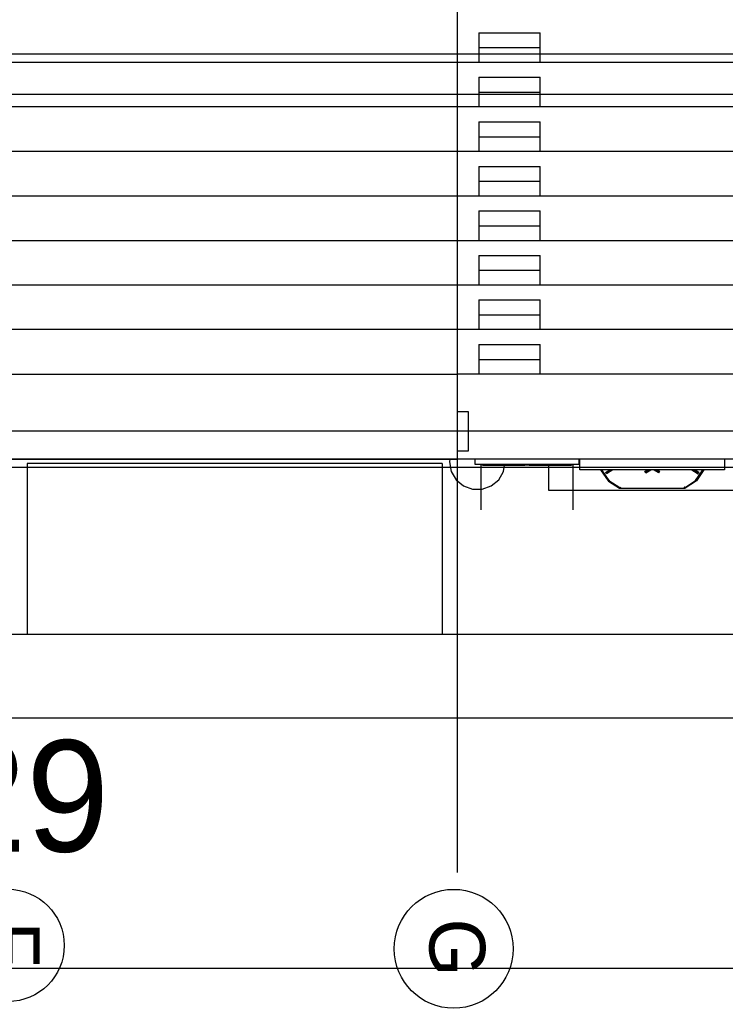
# Model space of a CAD drawing. Extents: x -264165 to -263575, y -1242333 to -1242036.
# Drawn here: x -263884.32 to -263871.66, y -1242251.17 to -1242233.41 of the extents above; entities that cross this region are included whole.
import ezdxf

# ---------------------------------------------------------------- set-up
doc = ezdxf.new("R2010")
doc.units = 0
for name, color, linetype in [('KFA_BODY_VYTYCOVAK', 7, 'Continuous'), ('KFA_HESCON_OSI_STAVBY', 7, 'Continuous'), ('KFA_SITUACIA_DRS_VYTYCOVAK_SEDA', 7, 'Continuous')]:
    doc.layers.add(name, color=color, linetype=linetype)

msp = doc.modelspace()

# ---------------------------------------------------------------- linework, layer by layer
at = {"layer": 'KFA_HESCON_OSI_STAVBY'}
for p, q in [((-263876.468, -1242080.447), (-263876.468, -1242248.737)), ((-263787.486, -1242234.032), (-263921.823, -1242234.032)), ((-263787.486, -1242240.807), (-263921.823, -1242240.807))]:
    msp.add_line(p, q, dxfattribs=at)
for centre, radius in [((-263884.533, -1242250.045), 1.008), ((-263876.533, -1242250.106), 1.068)]:
    msp.add_circle(centre, radius, dxfattribs=at)
at = {"layer": 'KFA_SITUACIA_DRS_VYTYCOVAK_SEDA'}
for p, q in [((-263876.081, -1242233.649), (-263876.081, -1242233.916)), ((-263876.081, -1242233.649), (-263876.081, -1242233.916)), ((-263876.081, -1242233.649), (-263874.981, -1242233.649)), ((-263876.081, -1242233.649), (-263874.981, -1242233.649)), ((-263874.981, -1242233.916), (-263874.981, -1242233.649)), ((-263874.981, -1242233.916), (-263874.981, -1242233.649)), ((-263876.081, -1242233.916), (-263874.981, -1242233.916)), ((-263876.081, -1242233.916), (-263874.981, -1242233.916)), ((-263876.081, -1242233.916), (-263876.081, -1242234.182)), ((-263876.081, -1242233.916), (-263876.081, -1242234.182)), ((-263874.981, -1242234.182), (-263874.981, -1242233.916)), ((-263874.981, -1242234.182), (-263874.981, -1242233.916)), ((-263876.468, -1242234.182), (-263884.468, -1242234.182)), ((-263876.468, -1242234.182), (-263884.468, -1242234.182)), ((-263869.468, -1242234.182), (-263876.468, -1242234.182)), ((-263869.468, -1242234.182), (-263876.468, -1242234.182)), ((-263876.081, -1242234.449), (-263876.081, -1242234.716)), ((-263876.081, -1242234.449), (-263876.081, -1242234.716)), ((-263876.081, -1242234.449), (-263874.981, -1242234.449)), ((-263876.081, -1242234.449), (-263874.981, -1242234.449)), ((-263874.981, -1242234.716), (-263874.981, -1242234.449)), ((-263874.981, -1242234.716), (-263874.981, -1242234.449)), ((-263876.081, -1242234.716), (-263874.981, -1242234.716)), ((-263876.081, -1242234.716), (-263874.981, -1242234.716)), ((-263876.081, -1242234.716), (-263876.081, -1242234.982)), ((-263876.081, -1242234.716), (-263876.081, -1242234.982)), ((-263874.981, -1242234.982), (-263874.981, -1242234.716)), ((-263874.981, -1242234.982), (-263874.981, -1242234.716)), ((-263812.068, -1242234.757), (-263891.868, -1242234.757)), ((-263876.468, -1242234.982), (-263884.468, -1242234.982)), ((-263876.468, -1242234.982), (-263884.468, -1242234.982)), ((-263869.468, -1242234.982), (-263876.468, -1242234.982)), ((-263869.468, -1242234.982), (-263876.468, -1242234.982)), ((-263876.081, -1242235.249), (-263876.081, -1242235.516)), ((-263876.081, -1242235.249), (-263876.081, -1242235.516)), ((-263876.081, -1242235.249), (-263874.981, -1242235.249)), ((-263876.081, -1242235.249), (-263874.981, -1242235.249)), ((-263874.981, -1242235.516), (-263874.981, -1242235.249)), ((-263874.981, -1242235.516), (-263874.981, -1242235.249)), ((-263876.081, -1242235.516), (-263874.981, -1242235.516)), ((-263876.081, -1242235.516), (-263874.981, -1242235.516)), ((-263876.081, -1242235.516), (-263876.081, -1242235.782)), ((-263876.081, -1242235.516), (-263876.081, -1242235.782)), ((-263874.981, -1242235.782), (-263874.981, -1242235.516)), ((-263874.981, -1242235.782), (-263874.981, -1242235.516)), ((-263876.468, -1242235.782), (-263884.468, -1242235.782)), ((-263876.468, -1242235.782), (-263884.468, -1242235.782)), ((-263869.468, -1242235.782), (-263876.468, -1242235.782)), ((-263869.468, -1242235.782), (-263876.468, -1242235.782)), ((-263876.081, -1242236.049), (-263876.081, -1242236.316)), ((-263876.081, -1242236.049), (-263876.081, -1242236.316)), ((-263876.081, -1242236.049), (-263874.981, -1242236.049)), ((-263876.081, -1242236.049), (-263874.981, -1242236.049)), ((-263874.981, -1242236.316), (-263874.981, -1242236.049)), ((-263874.981, -1242236.316), (-263874.981, -1242236.049)), ((-263876.081, -1242236.316), (-263874.981, -1242236.316)), ((-263876.081, -1242236.316), (-263874.981, -1242236.316)), ((-263876.081, -1242236.316), (-263876.081, -1242236.582)), ((-263876.081, -1242236.316), (-263876.081, -1242236.582)), ((-263874.981, -1242236.582), (-263874.981, -1242236.316)), ((-263874.981, -1242236.582), (-263874.981, -1242236.316)), ((-263876.468, -1242236.582), (-263884.468, -1242236.582)), ((-263876.468, -1242236.582), (-263884.468, -1242236.582)), ((-263869.468, -1242236.582), (-263876.468, -1242236.582)), ((-263869.468, -1242236.582), (-263876.468, -1242236.582)), ((-263876.081, -1242236.849), (-263876.081, -1242237.116)), ((-263876.081, -1242236.849), (-263876.081, -1242237.116)), ((-263876.081, -1242236.849), (-263874.981, -1242236.849)), ((-263876.081, -1242236.849), (-263874.981, -1242236.849)), ((-263874.981, -1242237.116), (-263874.981, -1242236.849)), ((-263874.981, -1242237.116), (-263874.981, -1242236.849)), ((-263876.081, -1242237.116), (-263874.981, -1242237.116)), ((-263876.081, -1242237.116), (-263874.981, -1242237.116)), ((-263876.081, -1242237.116), (-263876.081, -1242237.382)), ((-263876.081, -1242237.116), (-263876.081, -1242237.382)), ((-263874.981, -1242237.382), (-263874.981, -1242237.116)), ((-263874.981, -1242237.382), (-263874.981, -1242237.116)), ((-263884.468, -1242237.382), (-263876.468, -1242237.382)), ((-263884.468, -1242237.382), (-263876.468, -1242237.382)), ((-263876.468, -1242237.382), (-263869.468, -1242237.382)), ((-263876.468, -1242237.382), (-263869.468, -1242237.382)), ((-263876.081, -1242237.649), (-263876.081, -1242237.916)), ((-263876.081, -1242237.649), (-263876.081, -1242237.916)), ((-263876.081, -1242237.649), (-263874.981, -1242237.649)), ((-263876.081, -1242237.649), (-263874.981, -1242237.649)), ((-263874.981, -1242237.916), (-263874.981, -1242237.649)), ((-263874.981, -1242237.916), (-263874.981, -1242237.649)), ((-263876.081, -1242237.916), (-263874.981, -1242237.916)), ((-263876.081, -1242237.916), (-263874.981, -1242237.916)), ((-263876.081, -1242237.916), (-263876.081, -1242238.182)), ((-263876.081, -1242237.916), (-263876.081, -1242238.182)), ((-263874.981, -1242238.182), (-263874.981, -1242237.916)), ((-263874.981, -1242238.182), (-263874.981, -1242237.916)), ((-263876.468, -1242238.182), (-263884.468, -1242238.182)), ((-263876.468, -1242238.182), (-263884.468, -1242238.182)), ((-263869.468, -1242238.182), (-263876.468, -1242238.182)), ((-263869.468, -1242238.182), (-263876.468, -1242238.182)), ((-263876.081, -1242238.449), (-263876.081, -1242238.716)), ((-263876.081, -1242238.449), (-263876.081, -1242238.716)), ((-263876.081, -1242238.449), (-263874.981, -1242238.449)), ((-263876.081, -1242238.449), (-263874.981, -1242238.449)), ((-263874.981, -1242238.716), (-263874.981, -1242238.449)), ((-263874.981, -1242238.716), (-263874.981, -1242238.449)), ((-263876.081, -1242238.716), (-263874.981, -1242238.716)), ((-263876.081, -1242238.716), (-263874.981, -1242238.716)), ((-263876.081, -1242238.716), (-263876.081, -1242238.982)), ((-263876.081, -1242238.716), (-263876.081, -1242238.982)), ((-263874.981, -1242238.982), (-263874.981, -1242238.716)), ((-263874.981, -1242238.982), (-263874.981, -1242238.716)), ((-263876.468, -1242238.982), (-263884.468, -1242238.982)), ((-263876.468, -1242238.982), (-263884.468, -1242238.982)), ((-263869.468, -1242238.982), (-263876.468, -1242238.982)), ((-263869.468, -1242238.982), (-263876.468, -1242238.982)), ((-263876.081, -1242239.249), (-263876.081, -1242239.516)), ((-263876.081, -1242239.249), (-263876.081, -1242239.516)), ((-263876.081, -1242239.249), (-263874.981, -1242239.249)), ((-263876.081, -1242239.249), (-263874.981, -1242239.249)), ((-263874.981, -1242239.516), (-263874.981, -1242239.249)), ((-263874.981, -1242239.516), (-263874.981, -1242239.249)), ((-263876.081, -1242239.516), (-263874.981, -1242239.516)), ((-263876.081, -1242239.516), (-263874.981, -1242239.516)), ((-263876.081, -1242239.516), (-263876.081, -1242239.782)), ((-263876.081, -1242239.516), (-263876.081, -1242239.782)), ((-263874.981, -1242239.782), (-263874.981, -1242239.516)), ((-263874.981, -1242239.782), (-263874.981, -1242239.516)), ((-263884.468, -1242239.782), (-263876.468, -1242239.782)), ((-263884.468, -1242239.782), (-263876.468, -1242239.782)), ((-263869.468, -1242239.782), (-263876.468, -1242239.782)), ((-263869.468, -1242239.782), (-263876.468, -1242239.782)), ((-263876.268, -1242240.457), (-263876.468, -1242240.457)), ((-263876.268, -1242240.457), (-263876.468, -1242240.457)), ((-263876.468, -1242240.457), (-263876.468, -1242241.157)), ((-263876.468, -1242240.457), (-263876.468, -1242241.157)), ((-263876.268, -1242241.157), (-263876.268, -1242240.457)), ((-263876.268, -1242241.157), (-263876.268, -1242240.457)), ((-263884.468, -1242241.307), (-263876.468, -1242241.307)), ((-263884.468, -1242241.307), (-263876.468, -1242241.307)), ((-263876.478, -1242241.307), (-263884.458, -1242241.307)), ((-263876.478, -1242241.307), (-263884.458, -1242241.307)), ((-263876.599, -1242241.307), (-263876.608, -1242241.357)), ((-263876.599, -1242241.307), (-263876.608, -1242241.357)), ((-263876.458, -1242241.307), (-263876.478, -1242241.307)), ((-263876.458, -1242241.307), (-263876.478, -1242241.307)), ((-263876.468, -1242241.157), (-263876.268, -1242241.157)), ((-263876.468, -1242241.157), (-263876.268, -1242241.157)), ((-263869.468, -1242241.307), (-263876.468, -1242241.307)), ((-263869.468, -1242241.307), (-263876.468, -1242241.307)), ((-263869.478, -1242241.307), (-263876.458, -1242241.307)), ((-263869.478, -1242241.307), (-263876.458, -1242241.307)), ((-263876.148, -1242241.407), (-263876.148, -1242241.307)), ((-263876.148, -1242241.407), (-263876.148, -1242241.307)), ((-263874.288, -1242241.307), (-263874.288, -1242241.407)), ((-263874.288, -1242241.307), (-263874.288, -1242241.407)), ((-263874.268, -1242241.503), (-263874.268, -1242241.307)), ((-263874.268, -1242241.503), (-263874.268, -1242241.307)), ((-263871.668, -1242241.307), (-263871.668, -1242241.503)), ((-263871.668, -1242241.307), (-263871.668, -1242241.503)), ((-263808.968, -1242241.457), (-263894.968, -1242241.457)), ((-263884.188, -1242241.388), (-263884.188, -1242244.458)), ((-263884.188, -1242241.388), (-263884.188, -1242244.458)), ((-263876.738, -1242241.388), (-263884.188, -1242241.388)), ((-263876.738, -1242241.388), (-263884.188, -1242241.388)), ((-263876.738, -1242241.388), (-263876.738, -1242244.458)), ((-263876.738, -1242241.388), (-263876.738, -1242244.458)), ((-263876.608, -1242241.357), (-263876.578, -1242241.528)), ((-263876.608, -1242241.357), (-263876.578, -1242241.528)), ((-263874.288, -1242241.407), (-263876.148, -1242241.407)), ((-263874.288, -1242241.407), (-263876.148, -1242241.407)), ((-263876.043, -1242241.407), (-263876.043, -1242242.222)), ((-263876.043, -1242241.407), (-263876.043, -1242242.222)), ((-263876.043, -1242241.407), (-263876.017, -1242241.407)), ((-263876.043, -1242241.407), (-263876.017, -1242241.407)), ((-263876.017, -1242241.417), (-263876.017, -1242241.407)), ((-263876.017, -1242241.417), (-263876.017, -1242241.407)), ((-263876.017, -1242241.417), (-263875.258, -1242241.417)), ((-263876.017, -1242241.417), (-263875.258, -1242241.417)), ((-263875.638, -1242241.528), (-263875.618, -1242241.417)), ((-263875.638, -1242241.528), (-263875.618, -1242241.417)), ((-263875.258, -1242241.417), (-263875.258, -1242241.407)), ((-263875.258, -1242241.417), (-263875.258, -1242241.407)), ((-263875.258, -1242241.407), (-263875.228, -1242241.407)), ((-263875.258, -1242241.407), (-263875.228, -1242241.407)), ((-263875.258, -1242241.417), (-263875.258, -1242241.407)), ((-263875.258, -1242241.417), (-263875.258, -1242241.407)), ((-263875.178, -1242241.417), (-263875.258, -1242241.417)), ((-263875.178, -1242241.417), (-263875.258, -1242241.417)), ((-263875.208, -1242241.407), (-263875.177, -1242241.407)), ((-263875.208, -1242241.407), (-263875.177, -1242241.407)), ((-263875.178, -1242241.407), (-263875.178, -1242241.417)), ((-263875.178, -1242241.407), (-263875.178, -1242241.417)), ((-263875.177, -1242241.407), (-263875.177, -1242241.417)), ((-263875.177, -1242241.407), (-263875.177, -1242241.417)), ((-263875.177, -1242241.417), (-263874.418, -1242241.417)), ((-263875.177, -1242241.417), (-263874.418, -1242241.417)), ((-263874.828, -1242241.417), (-263874.828, -1242241.868)), ((-263874.828, -1242241.417), (-263874.828, -1242241.868)), ((-263874.418, -1242241.407), (-263874.393, -1242241.407)), ((-263874.418, -1242241.407), (-263874.393, -1242241.407)), ((-263874.418, -1242241.407), (-263874.418, -1242241.417)), ((-263874.418, -1242241.407), (-263874.418, -1242241.417)), ((-263874.393, -1242241.407), (-263874.393, -1242242.222)), ((-263874.393, -1242241.407), (-263874.393, -1242242.222)), ((-263876.578, -1242241.528), (-263876.491, -1242241.679)), ((-263876.578, -1242241.528), (-263876.491, -1242241.679)), ((-263875.725, -1242241.679), (-263875.638, -1242241.528)), ((-263875.725, -1242241.679), (-263875.638, -1242241.528)), ((-263871.668, -1242241.503), (-263874.268, -1242241.503)), ((-263871.668, -1242241.503), (-263874.268, -1242241.503)), ((-263873.889, -1242241.503), (-263873.754, -1242241.702)), ((-263873.889, -1242241.503), (-263873.754, -1242241.702)), ((-263873.754, -1242241.701), (-263873.889, -1242241.503)), ((-263873.754, -1242241.701), (-263873.889, -1242241.503)), ((-263873.877, -1242241.503), (-263873.746, -1242241.694)), ((-263873.877, -1242241.503), (-263873.746, -1242241.694)), ((-263873.873, -1242241.507), (-263873.874, -1242241.507)), ((-263873.873, -1242241.507), (-263873.874, -1242241.507)), ((-263873.873, -1242241.508), (-263873.874, -1242241.508)), ((-263873.873, -1242241.508), (-263873.874, -1242241.508)), ((-263873.872, -1242241.503), (-263873.873, -1242241.508)), ((-263873.872, -1242241.503), (-263873.873, -1242241.508)), ((-263873.872, -1242241.503), (-263873.873, -1242241.507)), ((-263873.872, -1242241.503), (-263873.873, -1242241.507)), ((-263873.806, -1242241.546), (-263873.732, -1242241.503)), ((-263873.806, -1242241.546), (-263873.732, -1242241.503)), ((-263873.806, -1242241.546), (-263873.797, -1242241.561)), ((-263873.806, -1242241.546), (-263873.797, -1242241.561)), ((-263873.797, -1242241.561), (-263873.698, -1242241.503)), ((-263873.797, -1242241.561), (-263873.698, -1242241.503)), ((-263873.792, -1242241.57), (-263873.797, -1242241.561)), ((-263873.792, -1242241.57), (-263873.797, -1242241.561)), ((-263873.677, -1242241.503), (-263873.792, -1242241.57)), ((-263873.677, -1242241.503), (-263873.792, -1242241.57)), ((-263873.047, -1242241.503), (-263873.099, -1242241.533)), ((-263873.047, -1242241.503), (-263873.099, -1242241.533)), ((-263873.099, -1242241.533), (-263873.047, -1242241.503)), ((-263873.099, -1242241.533), (-263873.047, -1242241.503)), ((-263873.099, -1242241.533), (-263873.093, -1242241.543)), ((-263873.099, -1242241.533), (-263873.093, -1242241.543)), ((-263873.093, -1242241.543), (-263873.099, -1242241.533)), ((-263873.093, -1242241.543), (-263873.099, -1242241.533)), ((-263873.025, -1242241.503), (-263873.093, -1242241.543)), ((-263873.025, -1242241.503), (-263873.093, -1242241.543)), ((-263873.085, -1242241.557), (-263873.093, -1242241.543)), ((-263873.085, -1242241.557), (-263873.093, -1242241.543)), ((-263873.085, -1242241.557), (-263873.093, -1242241.543)), ((-263873.085, -1242241.557), (-263873.093, -1242241.543)), ((-263873.085, -1242241.557), (-263872.991, -1242241.503)), ((-263873.085, -1242241.557), (-263872.991, -1242241.503)), ((-263872.85, -1242241.557), (-263872.943, -1242241.503)), ((-263872.85, -1242241.557), (-263872.943, -1242241.503)), ((-263872.841, -1242241.543), (-263872.909, -1242241.503)), ((-263872.841, -1242241.543), (-263872.909, -1242241.503)), ((-263872.888, -1242241.503), (-263872.836, -1242241.533)), ((-263872.888, -1242241.503), (-263872.836, -1242241.533)), ((-263872.836, -1242241.533), (-263872.888, -1242241.503)), ((-263872.836, -1242241.533), (-263872.888, -1242241.503)), ((-263872.85, -1242241.557), (-263872.841, -1242241.543)), ((-263872.85, -1242241.557), (-263872.841, -1242241.543)), ((-263872.85, -1242241.557), (-263872.841, -1242241.543)), ((-263872.85, -1242241.557), (-263872.841, -1242241.543)), ((-263872.836, -1242241.533), (-263872.841, -1242241.543)), ((-263872.836, -1242241.533), (-263872.841, -1242241.543)), ((-263872.841, -1242241.543), (-263872.836, -1242241.533)), ((-263872.841, -1242241.543), (-263872.836, -1242241.533)), ((-263872.258, -1242241.503), (-263872.143, -1242241.57)), ((-263872.258, -1242241.503), (-263872.143, -1242241.57)), ((-263872.237, -1242241.503), (-263872.137, -1242241.561)), ((-263872.237, -1242241.503), (-263872.137, -1242241.561)), ((-263872.129, -1242241.546), (-263872.203, -1242241.503)), ((-263872.129, -1242241.546), (-263872.203, -1242241.503)), ((-263872.189, -1242241.694), (-263872.058, -1242241.503)), ((-263872.189, -1242241.694), (-263872.058, -1242241.503)), ((-263872.183, -1242241.694), (-263872.052, -1242241.503)), ((-263872.183, -1242241.694), (-263872.052, -1242241.503)), ((-263872.04, -1242241.503), (-263872.175, -1242241.701)), ((-263872.04, -1242241.503), (-263872.175, -1242241.701)), ((-263872.143, -1242241.57), (-263872.137, -1242241.561)), ((-263872.143, -1242241.57), (-263872.137, -1242241.561)), ((-263872.129, -1242241.546), (-263872.137, -1242241.561)), ((-263872.129, -1242241.546), (-263872.137, -1242241.561)), ((-263872.063, -1242241.503), (-263872.061, -1242241.508)), ((-263872.063, -1242241.503), (-263872.061, -1242241.508)), ((-263872.061, -1242241.508), (-263872.061, -1242241.508)), ((-263872.061, -1242241.508), (-263872.061, -1242241.508)), ((-263876.491, -1242241.679), (-263876.358, -1242241.79)), ((-263876.491, -1242241.679), (-263876.358, -1242241.79)), ((-263876.358, -1242241.79), (-263876.195, -1242241.85)), ((-263876.358, -1242241.79), (-263876.195, -1242241.85)), ((-263876.021, -1242241.85), (-263875.858, -1242241.79)), ((-263876.021, -1242241.85), (-263875.858, -1242241.79)), ((-263875.858, -1242241.79), (-263875.725, -1242241.679)), ((-263875.858, -1242241.79), (-263875.725, -1242241.679)), ((-263873.554, -1242241.83), (-263873.754, -1242241.701)), ((-263873.554, -1242241.83), (-263873.754, -1242241.701)), ((-263873.754, -1242241.702), (-263873.554, -1242241.83)), ((-263873.754, -1242241.702), (-263873.554, -1242241.83)), ((-263873.746, -1242241.684), (-263873.751, -1242241.687)), ((-263873.746, -1242241.684), (-263873.751, -1242241.687)), ((-263873.746, -1242241.684), (-263873.737, -1242241.691)), ((-263873.746, -1242241.684), (-263873.737, -1242241.691)), ((-263873.746, -1242241.694), (-263873.549, -1242241.821)), ((-263873.746, -1242241.694), (-263873.549, -1242241.821)), ((-263873.737, -1242241.691), (-263873.739, -1242241.699)), ((-263873.737, -1242241.691), (-263873.739, -1242241.699)), ((-263873.737, -1242241.691), (-263873.739, -1242241.699)), ((-263873.737, -1242241.691), (-263873.739, -1242241.699)), ((-263873.737, -1242241.691), (-263873.737, -1242241.691)), ((-263873.737, -1242241.691), (-263873.737, -1242241.691)), ((-263873.556, -1242241.817), (-263873.549, -1242241.811)), ((-263873.556, -1242241.817), (-263873.549, -1242241.811)), ((-263873.549, -1242241.821), (-263873.554, -1242241.83)), ((-263873.549, -1242241.821), (-263873.554, -1242241.83)), ((-263873.554, -1242241.83), (-263873.549, -1242241.822)), ((-263873.554, -1242241.83), (-263873.549, -1242241.822)), ((-263873.554, -1242241.83), (-263873.543, -1242241.83)), ((-263873.554, -1242241.83), (-263873.543, -1242241.83)), ((-263873.554, -1242241.83), (-263873.543, -1242241.83)), ((-263873.554, -1242241.83), (-263873.543, -1242241.83)), ((-263873.543, -1242241.83), (-263873.554, -1242241.83)), ((-263873.543, -1242241.83), (-263873.554, -1242241.83)), ((-263873.554, -1242241.83), (-263873.543, -1242241.83)), ((-263873.554, -1242241.83), (-263873.543, -1242241.83)), ((-263873.543, -1242241.83), (-263873.554, -1242241.83)), ((-263873.543, -1242241.83), (-263873.554, -1242241.83)), ((-263873.554, -1242241.83), (-263873.548, -1242241.83)), ((-263873.554, -1242241.83), (-263873.548, -1242241.83)), ((-263873.549, -1242241.811), (-263873.539, -1242241.818)), ((-263873.549, -1242241.811), (-263873.539, -1242241.818)), ((-263873.548, -1242241.83), (-263872.383, -1242241.83)), ((-263873.548, -1242241.83), (-263872.383, -1242241.83)), ((-263873.548, -1242241.83), (-263873.548, -1242241.83)), ((-263873.548, -1242241.83), (-263873.548, -1242241.83)), ((-263873.539, -1242241.818), (-263873.543, -1242241.83)), ((-263873.539, -1242241.818), (-263873.543, -1242241.83)), ((-263873.539, -1242241.818), (-263873.543, -1242241.83)), ((-263873.539, -1242241.818), (-263873.543, -1242241.83)), ((-263873.539, -1242241.818), (-263873.539, -1242241.818)), ((-263873.539, -1242241.818), (-263873.539, -1242241.818)), ((-263872.386, -1242241.811), (-263872.396, -1242241.818)), ((-263872.386, -1242241.811), (-263872.396, -1242241.818)), ((-263872.396, -1242241.818), (-263872.392, -1242241.83)), ((-263872.396, -1242241.818), (-263872.392, -1242241.83)), ((-263872.384, -1242241.83), (-263872.392, -1242241.83)), ((-263872.384, -1242241.83), (-263872.392, -1242241.83)), ((-263872.384, -1242241.83), (-263872.392, -1242241.83)), ((-263872.384, -1242241.83), (-263872.392, -1242241.83)), ((-263872.392, -1242241.83), (-263872.384, -1242241.83)), ((-263872.392, -1242241.83), (-263872.384, -1242241.83)), ((-263872.391, -1242241.825), (-263872.387, -1242241.814)), ((-263872.391, -1242241.825), (-263872.387, -1242241.814)), ((-263872.381, -1242241.832), (-263872.391, -1242241.825)), ((-263872.381, -1242241.832), (-263872.391, -1242241.825)), ((-263872.387, -1242241.814), (-263872.375, -1242241.814)), ((-263872.387, -1242241.814), (-263872.375, -1242241.814)), ((-263872.386, -1242241.822), (-263872.189, -1242241.694)), ((-263872.386, -1242241.822), (-263872.189, -1242241.694)), ((-263872.383, -1242241.814), (-263872.386, -1242241.811)), ((-263872.383, -1242241.814), (-263872.386, -1242241.811)), ((-263872.381, -1242241.83), (-263872.386, -1242241.822)), ((-263872.381, -1242241.83), (-263872.386, -1242241.822)), ((-263872.381, -1242241.822), (-263872.183, -1242241.694)), ((-263872.381, -1242241.822), (-263872.183, -1242241.694)), ((-263872.375, -1242241.83), (-263872.381, -1242241.822)), ((-263872.375, -1242241.83), (-263872.381, -1242241.822)), ((-263872.377, -1242241.828), (-263872.381, -1242241.83)), ((-263872.377, -1242241.828), (-263872.381, -1242241.83)), ((-263872.381, -1242241.832), (-263872.376, -1242241.829)), ((-263872.381, -1242241.832), (-263872.376, -1242241.829)), ((-263872.379, -1242241.83), (-263872.375, -1242241.83)), ((-263872.379, -1242241.83), (-263872.375, -1242241.83)), ((-263872.175, -1242241.701), (-263872.375, -1242241.83)), ((-263872.175, -1242241.701), (-263872.375, -1242241.83)), ((-263872.375, -1242241.814), (-263872.375, -1242241.814)), ((-263872.375, -1242241.814), (-263872.375, -1242241.814)), ((-263872.189, -1242241.684), (-263872.198, -1242241.691)), ((-263872.189, -1242241.684), (-263872.198, -1242241.691)), ((-263872.198, -1242241.691), (-263872.196, -1242241.699)), ((-263872.198, -1242241.691), (-263872.196, -1242241.699)), ((-263872.192, -1242241.696), (-263872.189, -1242241.686)), ((-263872.192, -1242241.696), (-263872.189, -1242241.686)), ((-263872.186, -1242241.686), (-263872.189, -1242241.684)), ((-263872.186, -1242241.686), (-263872.189, -1242241.684)), ((-263872.183, -1242241.686), (-263872.189, -1242241.686)), ((-263872.183, -1242241.686), (-263872.189, -1242241.686)), ((-263876.195, -1242241.85), (-263876.021, -1242241.85)), ((-263876.195, -1242241.85), (-263876.021, -1242241.85)), ((-263874.828, -1242241.868), (-263871.108, -1242241.868)), ((-263874.828, -1242241.868), (-263871.108, -1242241.868)), ((-263851.968, -1242244.458), (-263896.21, -1242244.458)), ((-263876.738, -1242244.458), (-263884.188, -1242244.458)), ((-263876.738, -1242244.458), (-263884.188, -1242244.458)), ((-263896.71, -1242245.958), (-263808.225, -1242245.958)), ((-263807.725, -1242250.458), (-263917.593, -1242250.458))]:
    msp.add_line(p, q, dxfattribs=at)

# ---------------------------------------------------------------- texts
at = {"layer": 'KFA_BODY_VYTYCOVAK'}
msp.add_text('237.29', height=2, dxfattribs=at).set_placement((-263890.898, -1242248.36))
at = {"layer": 'KFA_HESCON_OSI_STAVBY'}
for s, p in [('G', (-263876.968, -1242249.562)), ('F', (-263884.968, -1242249.619))]:
    msp.add_text(s, height=1, rotation=270, dxfattribs=at).set_placement(p)

doc.saveas('drawing.dxf')
